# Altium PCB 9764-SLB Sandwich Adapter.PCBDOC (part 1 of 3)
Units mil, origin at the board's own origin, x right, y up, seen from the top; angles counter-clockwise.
Board outline 5593.84 x 1511.98 mil, 8 copper layers (Top Layer, MidLayer1, MidLayer2, MidLayer3, MidLayer4, MIdLayer5, MidLayer6, Bottom Layer); 137 components, 228 nets, 1508 pads, 0 vias.
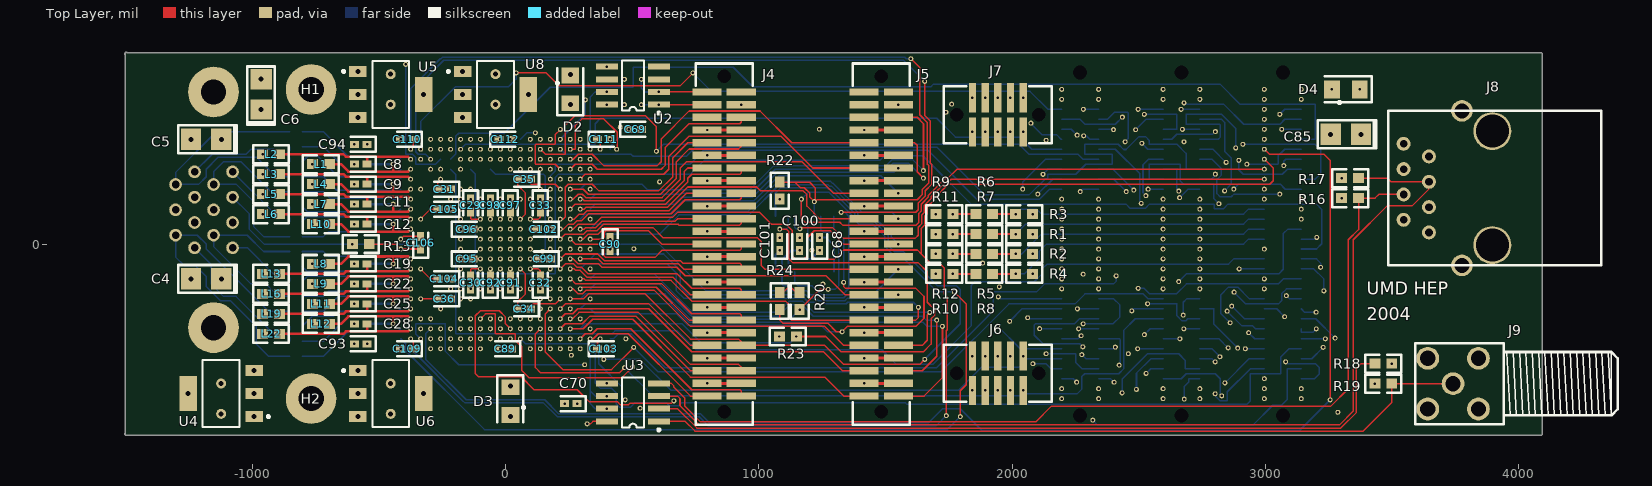
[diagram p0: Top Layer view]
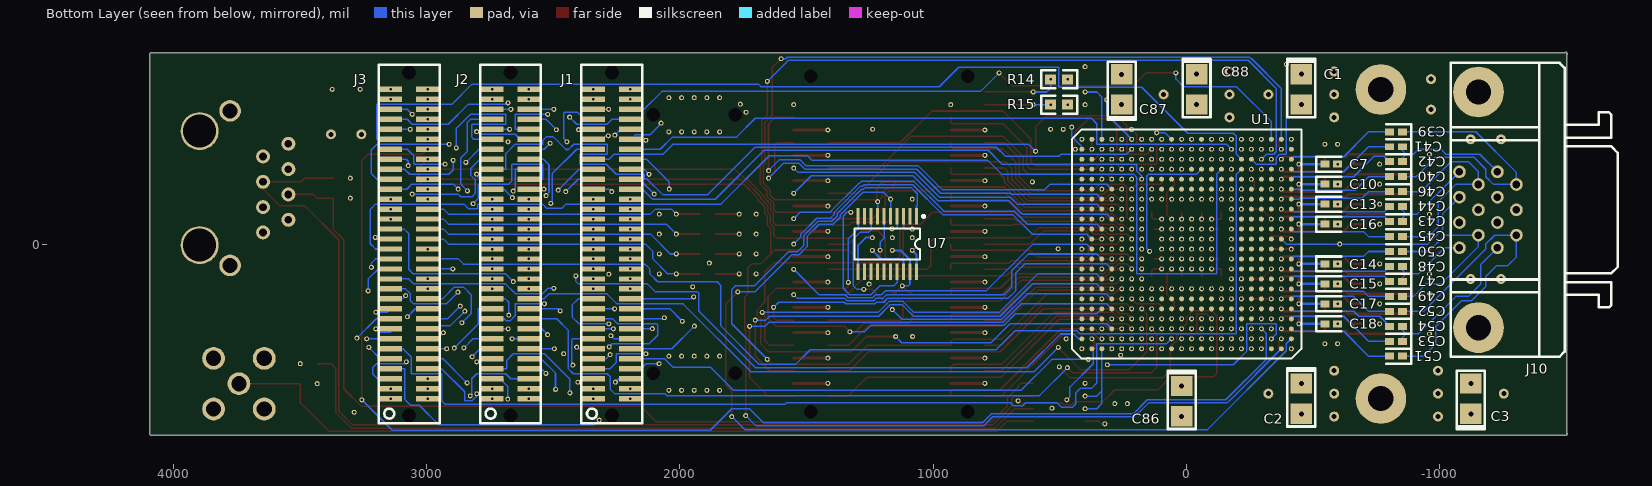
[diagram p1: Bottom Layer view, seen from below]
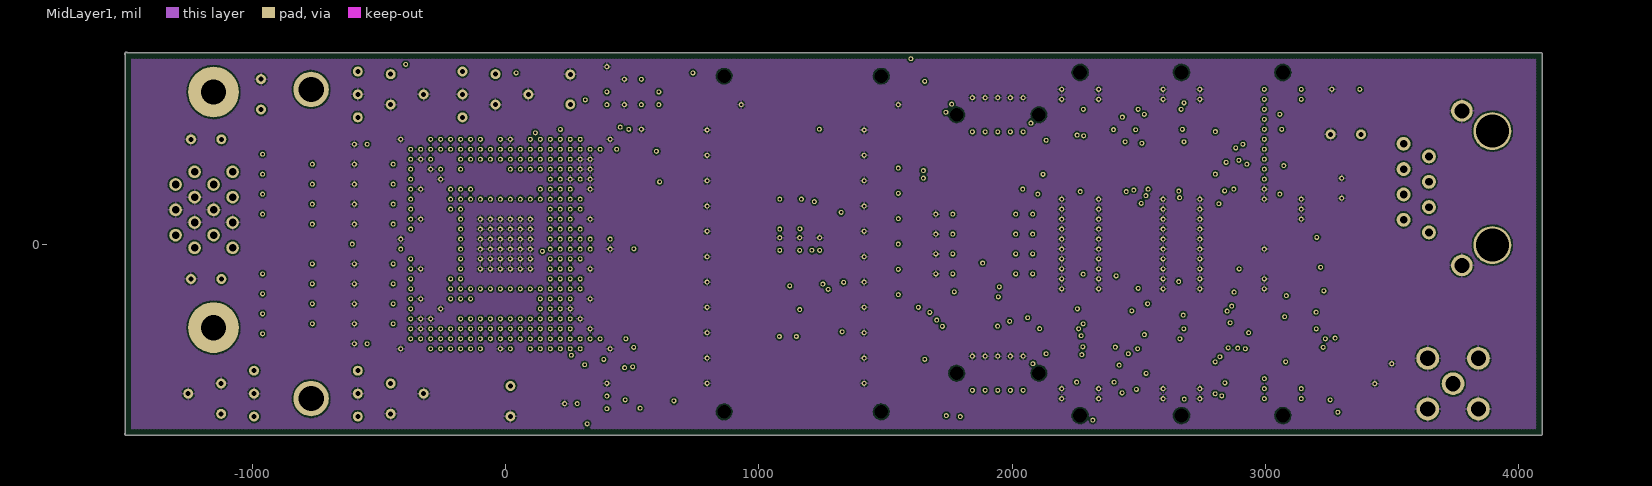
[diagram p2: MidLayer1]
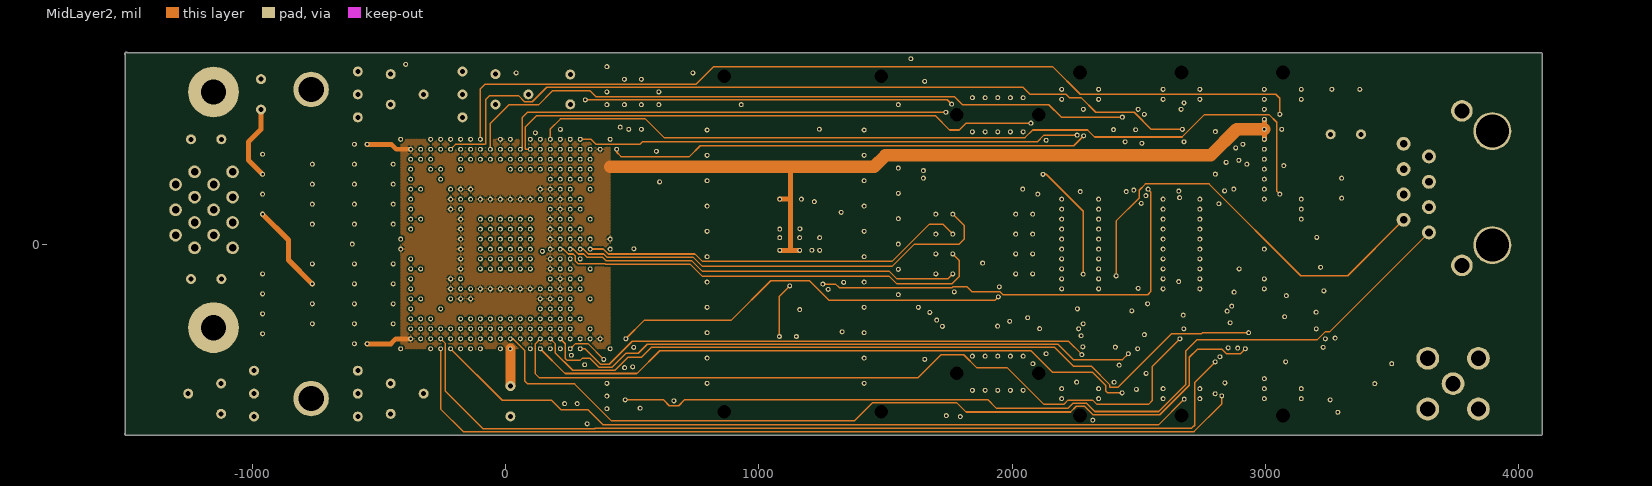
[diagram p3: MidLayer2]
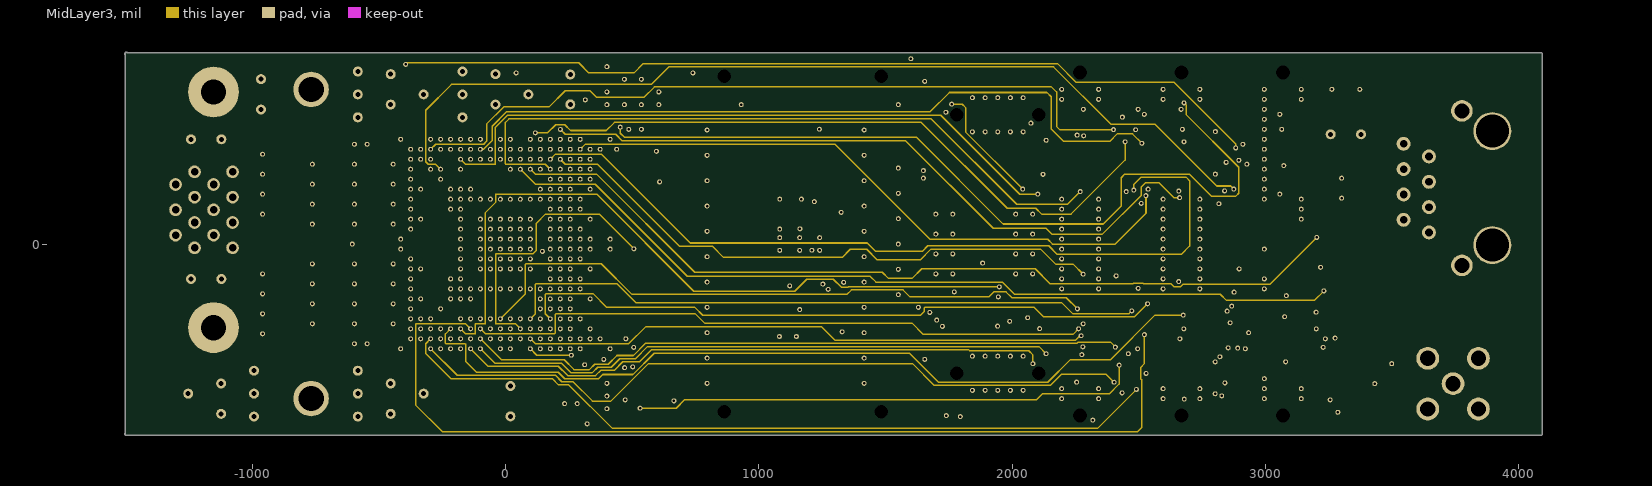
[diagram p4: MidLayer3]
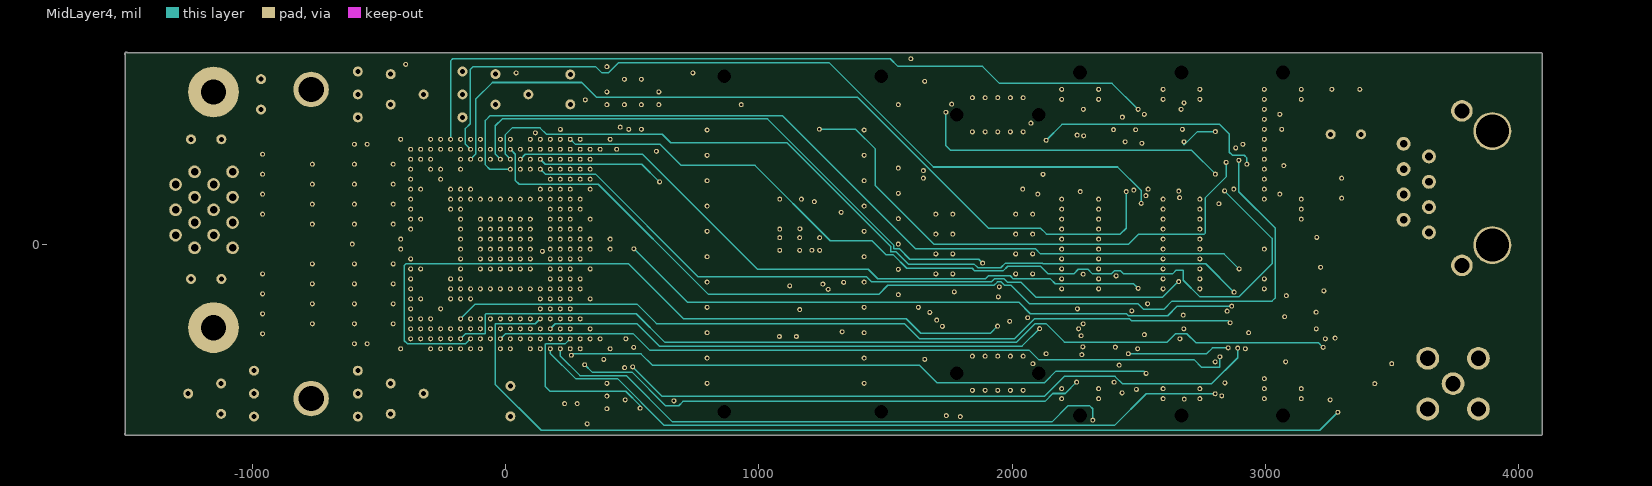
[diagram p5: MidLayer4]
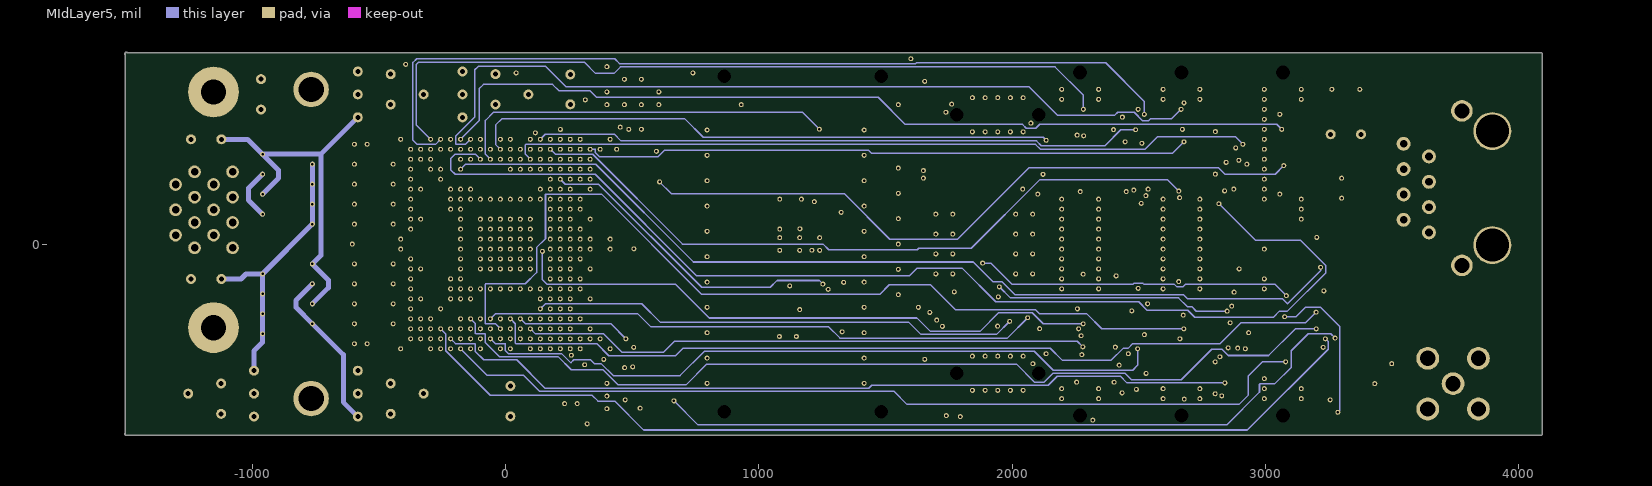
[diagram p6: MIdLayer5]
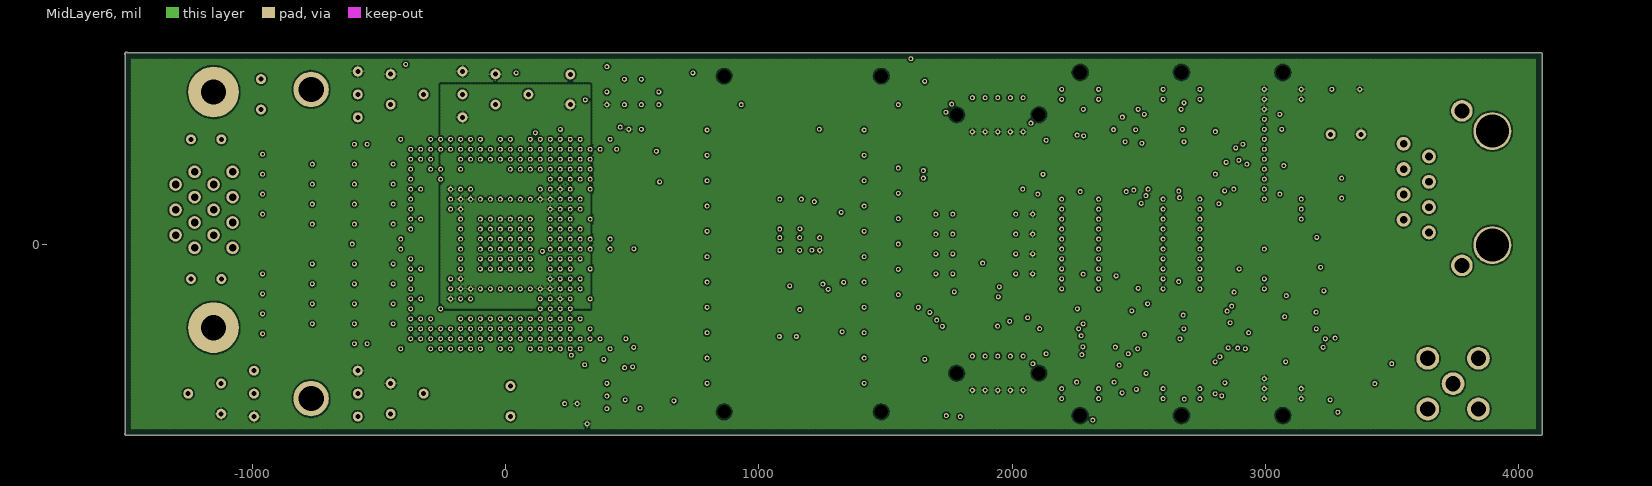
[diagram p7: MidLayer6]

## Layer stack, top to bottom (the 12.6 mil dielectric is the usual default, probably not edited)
Top Layer: signal copper 1.4
Dielectric: core 12.6, FR-4, Dk 4.8
MidLayer1: signal copper 1.4
Dielectric: prepreg 12.6, FR-4, Dk 4.8
MidLayer2: signal copper 1.4
Dielectric: core 12.6, FR-4, Dk 4.8
MidLayer3: signal copper 1.4
Dielectric: prepreg 12.6, FR-4, Dk 4.8
MidLayer4: signal copper 1.4
Dielectric: core 12.6, FR-4, Dk 4.8
MIdLayer5: signal copper 1.4
Dielectric: prepreg 12.6, FR-4, Dk 4.8
MidLayer6: signal copper 1.4
Dielectric: core 12.6, FR-4, Dk 4.8
Bottom Layer: signal copper 1.4

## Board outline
-1501.08,-747.3 -1501.08,747.3 cw(c-1496.85,750) -1501.01,752.8 cw(c-1496.06,751.97) -1492.08,755.01 4086.97,755.01 cw(c4086.97,750) 4091.98,750 4091.98,-750 cw(c4086.97,-750) 4086.97,-755.01 -1496.85,-755.01 cw(c-1496.85,-750)

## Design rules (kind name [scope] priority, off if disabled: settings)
Clearance [All] p1: gap=6
ComponentClearance [All] p1: gap=-10 collisioncheckmode=1
HoleSize [All] p1: absolutevalues=TRUE maxlimit=196.85 minlimit=9.84 maxpercent=80.000 minpercent=20.000
PlaneConnect PlaneConnect_1 [InNetClass('Power')] p1: planeconnectstyle=Relief reliefexpansion=20 reliefentries=4 reliefconductorwidth=10 reliefairgap=10
PlaneConnect [All] p2: planeconnectstyle=Relief reliefexpansion=15 reliefentries=4 reliefconductorwidth=6 reliefairgap=8
PolygonConnect [All] p1: connectstyle=Relief reliefconductorwidth=6 reliefentries=4 polygonreliefangle="90 Angle"
RoomDefinition "Power Supplies" [InComponentClass('Power Supplies')] p1: confinementstyle=ConfineIn formatcopy=TRUE outline -1751.97,-1348.43 25238.15,-1348.43 25238.15,5393.7 -1751.97,5393.7
RoomDefinition "Rocket IO" [InComponentClass('Rocket IO')] p2: confinementstyle=ConfineIn formatcopy=TRUE outline -1879.92,-1437.01 13938.15,-1437.01 13938.15,3464.57 -1879.92,3464.57
RoomDefinition "9764-SLB Sandwich Adapter" [InComponentClass('9764-SLB Sandwich Adapter')] p3: confinementstyle=ConfineIn formatcopy=TRUE outline -2361.85,-1750 18838.15,-1750 18838.15,9450 -2361.85,9450
RoutingLayers RoutingLayers_4 [InNet('GND')] p1: top layer_v5=FALSE mid layer 1_v5=TRUE mid layer 2_v5=FALSE mid layer 3_v5=FALSE mid layer 4_v5=FALSE mid layer 5_v5=FALSE mid layer 6_v5=FALSE bottom layer_v5=FALSE
RoutingLayers RoutingLayers_3 [InNet('+2.5V')] p2: top layer_v5=FALSE mid layer 1_v5=FALSE mid layer 2_v5=FALSE mid layer 3_v5=TRUE mid layer 4_v5=FALSE mid layer 5_v5=FALSE mid layer 6_v5=FALSE bottom layer_v5=FALSE
RoutingLayers RoutingLayers_2 [InNet('+3.3V')] p3: top layer_v5=FALSE mid layer 1_v5=FALSE mid layer 2_v5=TRUE mid layer 3_v5=FALSE mid layer 4_v5=FALSE mid layer 5_v5=FALSE mid layer 6_v5=FALSE bottom layer_v5=FALSE
RoutingLayers RoutingLayers_1 [InNet('+1.5V')] p4: top layer_v5=FALSE mid layer 1_v5=FALSE mid layer 2_v5=TRUE mid layer 3_v5=FALSE mid layer 4_v5=FALSE mid layer 5_v5=FALSE mid layer 6_v5=FALSE bottom layer_v5=FALSE
RoutingLayers [All] p5: top layer_v5=TRUE mid layer 1_v5=FALSE mid layer 2_v5=FALSE mid layer 3_v5=TRUE mid layer 4_v5=TRUE mid layer 5_v5=TRUE mid layer 6_v5=TRUE bottom layer_v5=TRUE
RoutingPriority RoutingPriority_1 [InNetClass('SLB/TTC')] p1: routingpriority=2
RoutingPriority [InNetClass('EPROM')] p2: routingpriority=0
RoutingVias [All] p1: holewidth=9.84 width=19.68 viastyle="Through Hole" minholewidth=9.84 minwidth=19.68 maxholewidth=78.74 maxwidth=157.48
SolderMaskExpansion [All] p1: expansion=4
TestPointUsage [All] p1: valid=0 allowmultiple=FALSE
Testpoint [All] p1: side=15 testpointundercomponent=TRUE minsize=40 maxsize=100 preferedsize=60 minholesize=0 maxholesize=40 preferedholesize=32 testpointgrid=1 style=1023 order=-539222988
Width [All] p1: maxlimit=100 minlimit=6 preferedwidth=10 toplayer_prefwidth=6 midlayer1_maxwidth=50 midlayer1_prefwidth=6 midlayer2_maxwidth=50 midlayer2_prefwidth=6 midlayer3_maxwidth=50 midlayer3_prefwidth=6 midlayer4_maxwidth=50 midlayer4_prefwidth=6 midlayer5_maxwidth=10 midlayer5_prefwidth=6 midlayer6_maxwidth=10 midlayer6_prefwidth=6 bottomlayer_prefwidth=6 minimp=50.000000 maximp=50.000000 favimp=50.000000
13 further rules are at their usual default settings.

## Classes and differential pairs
net class EPROM: CCLOCK DONE PROG_B PROM_INIT_B RECB3 TCK TDI TDI_F TDO TMS
net class 120MHz: ERRA ERRB ERRC ERRD IDLEA IDLEB IDLEC IDLED KCHA KCHB KCHC KCHD RECA0 RECA1 RECA2 RECA3 RECA4 RECA5 RECA6 RECA7 RECB0 RECB1 RECB2 RECB4 RECB5 RECB6 RECB7 RECC0 RECC1 RECC2 RECC3 RECC4 RECC5 RECC6 RECC7 RECD0 RECD1 RECD2 RECD3 RECD4 RECD5 RECD6 RECD7 RESETN TRSTN
net class RocketIO: \A \B \C \D \RX_A \RX_B \RX_C \RX_D \TX_A \TX_B \TX_C \TX_D A B C D NetR18_1 RX_A RX_B RX_C RX_D TX/R\X\ TX_A TX_B TX_C TX_D
net class SLB/TTC: LOC_C\S\ LOC_R/W\ LOCADD_0 LOCADD_1 LOCADD_2 LOCADD_3 LOCADD_4 LOCADD_5 LOCADD_6 LOCBUS_0 LOCBUS_1 LOCBUS_2 LOCBUS_3 LOCBUS_4 LOCBUS_5 LOCBUS_6 LOCBUS_7 LOCBUS_8 LOCBUS_9 LOCBUS_10 LOCBUS_11 LOCBUS_12 LOCBUS_13 LOCBUS_14 LOCBUS_15 SLB_ID TTC_BCR TTC_BRCST2 TTC_BRCST3 TTC_BRCST4 TTC_BRCST5 TTC_BRCST6 TTC_BRCST7 TTC_BRCST_STRB1 TTC_CLK_DES_1
net class Power: +1.5V +2.5V +3.3V AVCCAUX AVCCAUX1 AVCCAUX2 AVCCAUX3 AVCCAUX4 AVCCAUX5 AVCCAUX6 AVCCAUX7 AVCCAUX8 GND VTRX VTRX1 VTRX2 VTRX3 VTRX4 VTTX VTTX1 VTTX2 VTTX3 VTTX4
component class "Rocket IO": C39 C40 C41 C42 C43 C44 C45 C46 C47 C48 C49 C50 C51 C52 C53 C54 J10 J11
component class "9764-SLB Sandwich Adapter": J1 J2 J3 J4 J5 J6 J7 J8 J9 R1 R2 R3 R4 R5 R6 R7 R8 R9 R10 R11 R12 R13 R14 R15 R16 R17 R18 R19 U1 U2 U3
component class "Power Supplies": C1 C2 C3 C4 C5 C6 C7 C8 C9 C10 C11 C12 C13 C14 C15 C16 C17 C18 C19 C22 C25 C28 C29 C30 C31 C32 C33 C34 C35 C36 C61 C62 C63 C64 C65 C66 C67 C68 C69 C70 C71 C72 C73 C74 C75 C76 C77 C78 C79 C80 C81 C82 C83 C84 C85 C86 C87 C88 C89 C90 C91 C92 C93 C94 C95 C96 C97 C98 C99 C100 C101 C102 C103 C104 C105 C106 C107 C108 C109 C110 C111 C112 D2 D3 D4 H1 H2 H3 H4 H5 H6 L1 L2 L3 L4 L5 L6 L7 L8 L9 L10 L11 L12 L13 L16 L19 L22 R20 R22 R23 R24 U4 U5 U6 U7 U8
net class Clocks: BCO+ BCO- CLK+ CLK- NetJ8_4 NetJ8_5 NetJ9_1 PECL_OUT REFCLK REFCLK+ REFCLK- RX_BC0_INT+ RX_BC0_INT- RX_CLK_INT+ RX_CLK_INT- TP+ TP-

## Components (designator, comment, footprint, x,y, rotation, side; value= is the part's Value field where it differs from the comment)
C1 "10 uF" CT3528-1411 -452.76,610.24 r270 bottom
C2 "10 uF" CT3528-1411 -452.76,-610.24 r270 bottom
C3 "10 uF" CT3528-1411 -1122.05,-610.24 r90 bottom
C4 "10 uF" CT3528-1411 -1181.1,-137.8 r180 top
C5 "10 uF" CT3528-1411 -1181.1,413.39 r180 top
C6 "330 uF" CT3528-1411 -964.57,590.55 r90 top
C7 "1 uF" CC1005-0402 -570.87,314.96 r180 bottom
C8 "1 uF" CC1005-0402 -570.87,314.96 r180 top
C9 "1 uF" CC1005-0402 -570.87,236.22 r180 top
C10 "1 uF" CC1005-0402 -570.87,236.22 r180 bottom
C11 "1 uF" CC1005-0402 -570.87,157.48 r180 top
C12 "1 uF" CC1005-0402 -570.87,78.74 r180 top
C13 "1 uF" CC1005-0402 -570.87,157.48 r180 bottom
C14 "1 uF" CC1005-0402 -570.87,-78.74 r180 bottom
C15 "1 uF" CC1005-0402 -570.87,-157.48 r180 bottom
C16 "1 uF" CC1005-0402 -570.87,78.74 r180 bottom
C17 "1 uF" CC1005-0402 -570.87,-236.22 r180 bottom
C18 "1 uF" CC1005-0402 -570.87,-314.96 r180 bottom
C19 "1 uF" CC1005-0402 -570.87,-78.74 r180 top
C22 "1 uF" CC1005-0402 -570.87,-157.48 r180 top
C25 "1 uF" CC1005-0402 -570.87,-236.22 r180 top
C28 "1 uF" CC1005-0402 -570.87,-314.96 r180 top
C29 ".1 uF" CC1005-0402 -137.8,152.17 r270 top
C30 ".1 uF" CC1005-0402 -137.8,-152.17 r90 top
C31 ".1 uF" CC1005-0402 -241.54,216.54 r180 top
C32 ".1 uF" CC1005-0402 137.8,-152.17 r90 top
C33 ".1 uF" CC1005-0402 137.8,152.17 r270 top
C34 ".1 uF" CC1005-0402 73.43,-255.91 r180 top
C35 ".1 uF" CC1005-0402 73.43,255.91 r180 top
C36 ".1 uF" CC1005-0402 -241.54,-216.54 r180 top
C39 "1 uF" CC1005-0402 -826.77,442.91 r0 bottom
C40 "1 uF" CC1005-0402 -826.77,265.75 r0 bottom
C41 "1 uF" CC1005-0402 -826.77,383.86 r0 bottom
C42 "1 uF" CC1005-0402 -826.77,324.8 r0 bottom
C43 "1 uF" CC1005-0402 -826.77,88.58 r0 bottom
C44 "1 uF" CC1005-0402 -826.77,147.64 r0 bottom
C45 "1 uF" CC1005-0402 -826.77,29.53 r0 bottom
C46 "1 uF" CC1005-0402 -826.77,206.69 r0 bottom
C47 "1 uF" CC1005-0402 -826.77,-147.64 r0 bottom
C48 "1 uF" CC1005-0402 -826.77,-88.58 r0 bottom
C49 "1 uF" CC1005-0402 -826.77,-206.69 r0 bottom
C50 "1 uF" CC1005-0402 -826.77,-29.53 r0 bottom
C51 "1 uF" CC1005-0402 -826.77,-442.91 r0 bottom
C52 "1 uF" CC1005-0402 -826.77,-265.75 r0 bottom
C53 "1 uF" CC1005-0402 -826.77,-383.86 r0 bottom
C54 "1 uF" CC1005-0402 -826.77,-324.8 r0 bottom
C68 ".1 uF" CC1005-0402 1240.16,0 r90 top
C69 ".1 uF" CC1005-0402 511.81,452.76 r0 top
C70 ".1 uF" CC1005-0402 258.27,-629.92 r180 top
C85 "330 uF" CT3528-1411 3316.93,433.07 r180 top
C86 "330 uF" CT3528-1411 19.69,-620.08 r270 bottom
C87 "330 uF" CT3528-1411 255.91,610.24 r90 bottom
C88 "330 uF" CT3528-1411 -39.37,610.24 r270 bottom
C89 ".1 uF" CC1005-0402 0,-413.39 r180 top
C90 ".1 uF" CC1005-0402 413.39,0 r270 top
C91 ".1 uF" CC1005-0402 19.69,-152.17 r90 top
C92 ".1 uF" CC1005-0402 -59.06,-152.17 r90 top
C93 ".1 uF" CC1005-0402 -570.87,-393.7 r180 top
C94 ".1 uF" CC1005-0402 -570.87,393.7 r180 top
C95 ".1 uF" CC1005-0402 -152.17,-59.06 r0 top
C96 ".1 uF" CC1005-0402 -152.17,59.06 r0 top
C97 ".1 uF" CC1005-0402 19.69,152.17 r270 top
C98 ".1 uF" CC1005-0402 -59.06,152.17 r270 top
C99 ".1 uF" CC1005-0402 152.17,-59.06 r180 top
C100 ".1 uF" CC1005-0402 1161.42,0 r90 top
C101 ".1 uF" CC1005-0402 1082.68,0 r90 top
C102 ".1 uF" CC1005-0402 152.17,59.06 r180 top
C103 ".1 uF" CC1005-0402 388.39,-413.39 r0 top
C104 ".1 uF" CC1005-0402 -241.54,-137.8 r180 top
C105 ".1 uF" CC1005-0402 -241.54,137.8 r180 top
C106 ".1 uF" CC1005-0402 -334.65,5.32 r90 top
C109 ".1 uF" CC1005-0402 -388.39,-413.39 r180 top
C110 ".1 uF" CC1005-0402 -388.39,413.39 r180 top
C111 ".1 uF" CC1005-0402 388.39,413.39 r0 top
C112 ".1 uF" CC1005-0402 0,413.39 r0 top
D2 "LED" "HSMx-C150 LED" 255.91,610.24 r90 top
D3 "LED" "HSMx-C150 LED" 19.69,-620.08 r270 top
D4 "LED" "HSMx-C150 LED" 3316.93,610.24 r180 top
H1 "MH" "MOUNTING HOLE"#1 -767.72,669.29 r0 top
H2 "MH" "MOUNTING HOLE"#2 -787.4,-649.61 r0 top
J1 "MHDR2X32" MOLEX-71436-0464 2268.15,0 r0 bottom locked
J2 "MHDR2X32" MOLEX-71436-0464 2668.15,0 r0 bottom locked
J3 "MHDR2X32" MOLEX-71436-0464 3068.15,0 r0 bottom locked
J4 "" SAMTEC-TFM-150-XX-X-D 863.15,0 r180 top locked
J5 "" SAMTEC-TFM-150-XX-X-D 1483.15,0 r180 top locked
J6 "Connector 2X5" SAMTEC-TFM-110-XX-X-D 1943.15,-510 r90 top
J7 "Connector 2X5" SAMTEC-TFM-110-XX-X-D 1943.15,510 r90 top
J8 "558342-1" 558342-1 3894.97,220.56 r180 top
J9 "COAX" JOHNSON-SMA 3740.16,-551.18 r0 top
J10 "MDR-14" MDR-14 -1151.85,135 r90 bottom locked
L1 "1000" CR1608-0603 -728.35,314.96 r180 top
L2 "600" CR1608-0603 -925.2,354.33 r180 top
L3 "600" CR1608-0603 -925.2,275.59 r180 top
L4 "1000" CR1608-0603 -728.35,236.22 r180 top
L5 "600" CR1608-0603 -925.2,196.85 r180 top
L6 "600" CR1608-0603 -925.2,118.11 r180 top
L7 "600" CR1608-0603 -728.35,157.48 r180 top
L8 "600" CR1608-0603 -728.35,-78.74 r180 top
L9 "600" CR1608-0603 -728.35,-157.48 r180 top
L10 "600" CR1608-0603 -728.35,78.74 r180 top
L11 "600" CR1608-0603 -728.35,-236.22 r180 top
L12 "600" CR1608-0603 -728.35,-314.96 r180 top
L13 "600" CR1608-0603 -925.2,-118.11 r180 top
L16 "600" CR1608-0603 -925.2,-196.85 r180 top
L19 "600" CR1608-0603 -925.2,-275.59 r180 top
L22 "600" CR1608-0603 -925.2,-354.33 r180 top
R1 "130" CR1608-0603 2047.24,39.37 r180 top
R2 "130" CR1608-0603 2047.24,-39.37 r180 top
R3 "130" CR1608-0603 2047.24,118.11 r180 top
R4 "130" CR1608-0603 2047.24,-118.11 r180 top
R5 "27" CR1608-0603 1889.76,-39.37 r180 top
R6 "27" CR1608-0603 1889.76,118.11 r180 top
R7 "27" CR1608-0603 1889.76,39.37 r180 top
R8 "27" CR1608-0603 1889.76,-118.11 r180 top
R9 "56" CR1608-0603 1732.28,118.11 r0 top
R10 "56" CR1608-0603 1732.28,-118.11 r0 top
R11 "56" CR1608-0603 1732.28,39.37 r0 top
R12 "56" CR1608-0603 1732.28,-39.37 r0 top
R13 "50" CR1608-0603 -570.87,0 r180 top
R14 "50" CR1608-0603 503.15,650 r180 bottom
R15 "50" CR1608-0603 503.15,550 r180 bottom
R16 "50" CR1608-0603 3333.55,181.19 r180 top
R17 "50" CR1608-0603 3333.55,259.93 r180 top
R18 "50" CR1608-0603 3464.57,-472.44 r0 top
R19 "50" CR1608-0603 3464.57,-551.18 r180 top
R20 "4.7 k" CR1608-0603 1161.42,-225 r90 top
R22 "4.7 k" CR1608-0603 1082.68,210.63 r270 top
R23 "4.7 k" CR1608-0603 1115,-365 r180 top
R24 "4.7 k" CR1608-0603 1082.68,-225 r90 top
U1 "XC2VP7-5FG456C" FG456 0,0 r270 bottom locked
U2 "MC100EPT22D" 751-06 503.15,625 r90 top
U3 "MC100EPT22D" 751-06 503.15,-625 r90 top
U4 "#NAME?" SOT-223 -1122.05,-590.55 r90 top
U5 "#NAME?" SOT-223 -452.76,590.55 r270 top
U6 "#NAME?" SOT-223 -452.76,-590.55 r270 top
U7 "XCF04SVO20C" VO20 1181.1,0 r0 bottom
U8 "#NAME?" SOT-223 -39.37,590.55 r270 top

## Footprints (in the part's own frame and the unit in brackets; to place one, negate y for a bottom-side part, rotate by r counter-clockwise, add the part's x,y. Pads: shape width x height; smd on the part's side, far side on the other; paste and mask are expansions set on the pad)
751-06 [mm] "Small Outline; 8 Leads; Body Width 3.9 mm; Pitch 1.27 mm"
  rect 0.6x2.2 smd: 1(-1.905,-2.6) 2(-0.635,-2.6) 3(0.635,-2.6) 4(1.905,-2.6) 5(1.905,2.6) 6(0.635,2.6) 7(-0.635,2.6) 8(-1.905,2.6)
  silkscreen extent -2.88,-2.72 2.5,1.1
558342-1 [mil] "8 pin Sheilded Right Angle RJ-45 Cat 5 Connector"
  round 150 hole 130 unplated: 0(0,225) 0(0,-225)
  round 85 hole 60: 0(120,305) 0(120,-305)
  round 55 hole 30: 1(350,125) 2(250,175) 3(250,75) 4(250,-25) 5(350,25) 6(350,-75) 7(350,-175) 8(250,-125)
  silkscreen extent -430,-305 410,305
CC1005-0402 [mm]
  rect 0.9x0.7 smd: 1(-0.635,0) 2(0.635,0)
  silkscreen extent -1.5,-0.75 1,0.75
CR1608-0603 [mm]
  rect 1.1x1 smd: 1(-0.85,0) 2(0.85,0)
  silkscreen extent -1.8,-0.9 1.8,0.9
CT3528-1411 [mil] "Tantalum Electrolytic Capacitor"
  rect 80x85 smd: 1(-60,0) 2(60,0)
  silkscreen extent -120,-55 110,55
FG456 [mm]
  round 0.5 hole 0.25: A1(-10.5,10.5) A11(-0.5,10.5) A12(0.5,10.5) A22(10.5,10.5) AA2(-9.5,-9.5) AA21(9.5,-9.5) AB1(-10.5,-10.5) AB11(-0.5,-10.5) AB12(0.5,-10.5) AB22(10.5,-10.5) B2(-9.5,9.5) B3(-8.5,9.5) B4(-7.5,9.5) B5(-6.5,9.5) B6(-5.5,9.5) B7(-4.5,9.5) B8(-3.5,9.5) B9(-2.5,9.5) B10(-1.5,9.5) B13(1.5,9.5) B14(2.5,9.5) B15(3.5,9.5) B16(4.5,9.5) B17(5.5,9.5) B18(6.5,9.5) B19(7.5,9.5) B20(8.5,9.5) B21(9.5,9.5) C2(-9.5,8.5) C3(-8.5,8.5) C6(-5.5,8.5) C9(-2.5,8.5) C14(2.5,8.5) C17(5.5,8.5) C19(7.5,8.5) C20(8.5,8.5) C21(9.5,8.5) D1(-10.5,7.5) D2(-9.5,7.5) D3(-8.5,7.5) D4(-7.5,7.5) D19(7.5,7.5) D20(8.5,7.5) D21(9.5,7.5) D22(10.5,7.5) E1(-10.5,6.5) E2(-9.5,6.5) E4(-7.5,6.5) E5(-6.5,6.5) E18(6.5,6.5) E20(8.5,6.5) E21(9.5,6.5) E22(10.5,6.5) F1(-10.5,5.5) F2(-9.5,5.5) F6(-5.5,5.5) F7(-4.5,5.5) F8(-3.5,5.5) F15(3.5,5.5) F16(4.5,5.5) F17(5.5,5.5) F20(8.5,5.5) F21(9.5,5.5) F22(10.5,5.5) G1(-10.5,4.5) G2(-9.5,4.5) G3(-8.5,4.5) G4(-7.5,4.5) G6(-5.5,4.5) G7(-4.5,4.5) G8(-3.5,4.5) G9(-2.5,4.5) G10(-1.5,4.5) G11(-0.5,4.5) G12(0.5,4.5) G13(1.5,4.5) G14(2.5,4.5) G15(3.5,4.5) G16(4.5,4.5) G17(5.5,4.5) G19(7.5,4.5) G20(8.5,4.5) G21(9.5,4.5) G22(10.5,4.5) H1(-10.5,3.5) H2(-9.5,3.5) H3(-8.5,3.5) H6(-5.5,3.5) H7(-4.5,3.5) H16(4.5,3.5) H17(5.5,3.5) H19(7.5,3.5) H20(8.5,3.5) H21(9.5,3.5) H22(10.5,3.5) J1(-10.5,2.5) J2(-9.5,2.5) J3(-8.5,2.5) J7(-4.5,2.5) J9(-2.5,2.5) J10(-1.5,2.5) J11(-0.5,2.5) J12(0.5,2.5) J13(1.5,2.5) J14(2.5,2.5) J16(4.5,2.5) J19(7.5,2.5) J20(8.5,2.5) J21(9.5,2.5) J22(10.5,2.5) K2(-9.5,1.5) K3(-8.5,1.5) K7(-4.5,1.5) K9(-2.5,1.5) K10(-1.5,1.5) K11(-0.5,1.5) K12(0.5,1.5) K13(1.5,1.5) K14(2.5,1.5) K16(4.5,1.5) K19(7.5,1.5) K20(8.5,1.5) K21(9.5,1.5) L1(-10.5,0.5) L2(-9.5,0.5) L3(-8.5,0.5) L7(-4.5,0.5) L9(-2.5,0.5) L10(-1.5,0.5) L11(-0.5,0.5) L12(0.5,0.5) L13(1.5,0.5) L14(2.5,0.5) L16(4.5,0.5) L19(7.5,0.5) L20(8.5,0.5) L21(9.5,0.5) L22(10.5,0.5) M1(-10.5,-0.5) M2(-9.5,-0.5) M3(-8.5,-0.5) M4(-7.5,-0.5) M7(-4.5,-0.5) M9(-2.5,-0.5) M10(-1.5,-0.5) M11(-0.5,-0.5) M12(0.5,-0.5) M13(1.5,-0.5) M14(2.5,-0.5) M16(4.5,-0.5) M19(7.5,-0.5) M20(8.5,-0.5) M21(9.5,-0.5) M22(10.5,-0.5) N2(-9.5,-1.5) N3(-8.5,-1.5) N4(-7.5,-1.5) N7(-4.5,-1.5) N9(-2.5,-1.5) N10(-1.5,-1.5) N11(-0.5,-1.5) N12(0.5,-1.5) N13(1.5,-1.5) N14(2.5,-1.5) N16(4.5,-1.5) N19(7.5,-1.5) N20(8.5,-1.5) N21(9.5,-1.5) P1(-10.5,-2.5) P2(-9.5,-2.5) P3(-8.5,-2.5) P4(-7.5,-2.5) P7(-4.5,-2.5) P9(-2.5,-2.5) P10(-1.5,-2.5) P11(-0.5,-2.5) P12(0.5,-2.5) P13(1.5,-2.5) P14(2.5,-2.5) P16(4.5,-2.5) P19(7.5,-2.5) P20(8.5,-2.5) P21(9.5,-2.5) P22(10.5,-2.5) R1(-10.5,-3.5) R2(-9.5,-3.5) R3(-8.5,-3.5) R4(-7.5,-3.5) R6(-5.5,-3.5) R7(-4.5,-3.5) R16(4.5,-3.5) R17(5.5,-3.5) R18(6.5,-3.5) R19(7.5,-3.5) R20(8.5,-3.5) R21(9.5,-3.5) R22(10.5,-3.5) T1(-10.5,-4.5) T2(-9.5,-4.5) T3(-8.5,-4.5) T4(-7.5,-4.5) T5(-6.5,-4.5) T6(-5.5,-4.5) T7(-4.5,-4.5) T8(-3.5,-4.5) T9(-2.5,-4.5) T10(-1.5,-4.5) T11(-0.5,-4.5) T12(0.5,-4.5) T13(1.5,-4.5) T14(2.5,-4.5) T15(3.5,-4.5) T16(4.5,-4.5) T17(5.5,-4.5) T18(6.5,-4.5) T19(7.5,-4.5) T20(8.5,-4.5) T21(9.5,-4.5) T22(10.5,-4.5) U1(-10.5,-5.5) U2(-9.5,-5.5) U3(-8.5,-5.5) U4(-7.5,-5.5) U5(-6.5,-5.5) U6(-5.5,-5.5) U7(-4.5,-5.5) U8(-3.5,-5.5) U9(-2.5,-5.5) U10(-1.5,-5.5) U11(-0.5,-5.5) U12(0.5,-5.5) U13(1.5,-5.5) U14(2.5,-5.5) U15(3.5,-5.5) U16(4.5,-5.5) U17(5.5,-5.5) U18(6.5,-5.5) U19(7.5,-5.5) U20(8.5,-5.5) U21(9.5,-5.5) U22(10.5,-5.5) V1(-10.5,-6.5) V2(-9.5,-6.5) V3(-8.5,-6.5) V4(-7.5,-6.5) V5(-6.5,-6.5) V6(-5.5,-6.5) V7(-4.5,-6.5) V8(-3.5,-6.5) V9(-2.5,-6.5) V10(-1.5,-6.5) V11(-0.5,-6.5) V12(0.5,-6.5) V13(1.5,-6.5) V14(2.5,-6.5) V15(3.5,-6.5) V16(4.5,-6.5) V17(5.5,-6.5) V18(6.5,-6.5) V19(7.5,-6.5) V20(8.5,-6.5) V21(9.5,-6.5) V22(10.5,-6.5) W1(-10.5,-7.5) W2(-9.5,-7.5) W3(-8.5,-7.5) W4(-7.5,-7.5) W5(-6.5,-7.5) W7(-4.5,-7.5) W8(-3.5,-7.5) W10(-1.5,-7.5) W11(-0.5,-7.5) W12(0.5,-7.5) W13(1.5,-7.5) W15(3.5,-7.5) W16(4.5,-7.5) W19(7.5,-7.5) W21(9.5,-7.5) W22(10.5,-7.5) Y2(-9.5,-8.5) Y3(-8.5,-8.5) Y4(-7.5,-8.5) Y5(-6.5,-8.5) Y6(-5.5,-8.5) Y9(-2.5,-8.5) Y11(-0.5,-8.5) Y12(0.5,-8.5) Y14(2.5,-8.5) Y17(5.5,-8.5) Y20(8.5,-8.5) Y21(9.5,-8.5)
  round 0.5 smd: A2(-9.5,10.5) A3(-8.5,10.5) A4(-7.5,10.5) A5(-6.5,10.5) A6(-5.5,10.5) A7(-4.5,10.5) A8(-3.5,10.5) A9(-2.5,10.5) A10(-1.5,10.5) A13(1.5,10.5) A14(2.5,10.5) A15(3.5,10.5) A16(4.5,10.5) A17(5.5,10.5) A18(6.5,10.5) A19(7.5,10.5) A20(8.5,10.5) A21(9.5,10.5) AA1(-10.5,-9.5) AA3(-8.5,-9.5) AA4(-7.5,-9.5) AA5(-6.5,-9.5) AA6(-5.5,-9.5) AA7(-4.5,-9.5) AA8(-3.5,-9.5) AA9(-2.5,-9.5) AA10(-1.5,-9.5) AA11(-0.5,-9.5) AA12(0.5,-9.5) AA13(1.5,-9.5) AA14(2.5,-9.5) AA15(3.5,-9.5) AA16(4.5,-9.5) AA17(5.5,-9.5) AA18(6.5,-9.5) AA19(7.5,-9.5) AA20(8.5,-9.5) AA22(10.5,-9.5) AB2(-9.5,-10.5) AB3(-8.5,-10.5) AB4(-7.5,-10.5) AB5(-6.5,-10.5) AB6(-5.5,-10.5) AB7(-4.5,-10.5) AB8(-3.5,-10.5) AB9(-2.5,-10.5) AB10(-1.5,-10.5) AB13(1.5,-10.5) AB14(2.5,-10.5) AB15(3.5,-10.5) AB16(4.5,-10.5) AB17(5.5,-10.5) AB18(6.5,-10.5) AB19(7.5,-10.5) AB20(8.5,-10.5) AB21(9.5,-10.5) B1(-10.5,9.5) B11(-0.5,9.5) B12(0.5,9.5) B22(10.5,9.5) C1(-10.5,8.5) C4(-7.5,8.5) C5(-6.5,8.5) C7(-4.5,8.5) C8(-3.5,8.5) C10(-1.5,8.5) C11(-0.5,8.5) C12(0.5,8.5) C13(1.5,8.5) C15(3.5,8.5) C16(4.5,8.5) C18(6.5,8.5) C22(10.5,8.5) D5(-6.5,7.5) D6(-5.5,7.5) D7(-4.5,7.5) D8(-3.5,7.5) D9(-2.5,7.5) D10(-1.5,7.5) D11(-0.5,7.5) D12(0.5,7.5) D13(1.5,7.5) D14(2.5,7.5) D15(3.5,7.5) D16(4.5,7.5) D17(5.5,7.5) D18(6.5,7.5) E3(-8.5,6.5) E6(-5.5,6.5) E7(-4.5,6.5) E8(-3.5,6.5) E9(-2.5,6.5) E10(-1.5,6.5) E11(-0.5,6.5) E12(0.5,6.5) E13(1.5,6.5) E14(2.5,6.5) E15(3.5,6.5) E16(4.5,6.5) E17(5.5,6.5) E19(7.5,6.5) F3(-8.5,5.5) F4(-7.5,5.5) F5(-6.5,5.5) F9(-2.5,5.5) F10(-1.5,5.5) F11(-0.5,5.5) F12(0.5,5.5) F13(1.5,5.5) F14(2.5,5.5) F18(6.5,5.5) F19(7.5,5.5) G5(-6.5,4.5) G18(6.5,4.5) H4(-7.5,3.5) H5(-6.5,3.5) H18(6.5,3.5) J4(-7.5,2.5) J5(-6.5,2.5) J6(-5.5,2.5) J17(5.5,2.5) J18(6.5,2.5) K1(-10.5,1.5) K4(-7.5,1.5) K5(-6.5,1.5) K6(-5.5,1.5) K17(5.5,1.5) K18(6.5,1.5) K22(10.5,1.5) L4(-7.5,0.5) L5(-6.5,0.5) L6(-5.5,0.5) L17(5.5,0.5) L18(6.5,0.5) M5(-6.5,-0.5) M6(-5.5,-0.5) M17(5.5,-0.5) M18(6.5,-0.5) N1(-10.5,-1.5) N5(-6.5,-1.5) N6(-5.5,-1.5) N17(5.5,-1.5) N18(6.5,-1.5) N22(10.5,-1.5) P5(-6.5,-2.5) P6(-5.5,-2.5) P17(5.5,-2.5) P18(6.5,-2.5) R5(-6.5,-3.5) W6(-5.5,-7.5) W9(-2.5,-7.5) W14(2.5,-7.5) W17(5.5,-7.5) W18(6.5,-7.5) W20(8.5,-7.5) Y1(-10.5,-8.5) Y7(-4.5,-8.5) Y8(-3.5,-8.5) Y10(-1.5,-8.5) Y13(1.5,-8.5) Y15(3.5,-8.5) Y16(4.5,-8.5) Y18(6.5,-8.5) Y19(7.5,-8.5) Y22(10.5,-8.5)
  silkscreen extent -11.5,-11.5 11.5,11.5
"HSMx-C150 LED" [mil] "Surface Mount Chip LED"
  rect 62x70 smd: 1(-55,0) 2(55,0)
  silkscreen extent -102,-51 83,56
JOHNSON-SMA [mil] "Johnson-SMA"
  round 90 hole 60: 1(0,0) 2(-100,-100) 2(-100,100) 2(100,-100) 2(100,100)
  silkscreen extent -150,-160 650,160
MDR-14 [mil]
  round 200 hole 100: 0(-465,0) 0(465,0)
  round 50 hole 30: 1(150,75) 2(100,0) 3(50,75) 4(0,0) 5(-50,75) 6(-100,0) 7(-150,75) 8(150,-75) 9(100,-150) 10(50,-75) 11(0,-150) 12(-50,-75) 13(-100,-150) 14(-150,-75)
  silkscreen extent -580,-550 580,110
MOLEX-71436-0464 [mm] "64 Position Male Mezzanine Connector"
  round 0 hole 1.4 unplated: 0(0,-17.2) 0(0,17.2)
  rect 2.3x0.533 smd: 1(1.85,15.5) 2(-1.85,15.5) 3(1.85,14.5) 4(-1.85,14.5) 5(1.85,13.5) 6(-1.85,13.5) 7(1.85,12.5) 8(-1.85,12.5) 9(1.85,11.5) 10(-1.85,11.5) 11(1.85,10.5) 12(-1.85,10.5) 13(1.85,9.5) 14(-1.85,9.5) 15(1.85,8.5) 16(-1.85,8.5) 17(1.85,7.5) 18(-1.85,7.5) 19(1.85,6.5) 20(-1.85,6.5) 21(1.85,5.5) 22(-1.85,5.5) 23(1.85,4.5) 24(-1.85,4.5) 25(1.85,3.5) 26(-1.85,3.5) 27(1.85,2.5) 28(-1.85,2.5) 29(1.85,1.5) 30(-1.85,1.5) 31(1.85,0.5) 32(-1.85,0.5) 33(1.85,-0.5) 34(-1.85,-0.5) 35(1.85,-1.5) 36(-1.85,-1.5) 37(1.85,-2.5) 38(-1.85,-2.5) 39(1.85,-3.5) 40(-1.85,-3.5) 41(1.85,-4.5) 42(-1.85,-4.5) 43(1.85,-5.5) 44(-1.85,-5.5) 45(1.85,-6.5) 46(-1.85,-6.5) 47(1.85,-7.5) 48(-1.85,-7.5) 49(1.85,-8.5) 50(-1.85,-8.5) 51(1.85,-9.5) 52(-1.85,-9.5) 53(1.85,-10.5) 54(-1.85,-10.5) 55(1.85,-11.5) 56(-1.85,-11.5) 57(1.85,-12.5) 58(-1.85,-12.5) 59(1.85,-13.5) 60(-1.85,-13.5) 61(1.85,-14.5) 62(-1.85,-14.5) 63(1.85,-15.5) 64(-1.85,-15.5)
  silkscreen extent -3.05,-17.95 3.05,17.95
"MOUNTING HOLE"#1 [mil]
  round 200 / inner round 140 / far side round 200 hole 100: 1(0.87,-59.29)
"MOUNTING HOLE"#2 [mil]
  round 200 / inner round 140 / far side round 200 hole 100: 1(20.55,39.61)
SAMTEC-TFM-110-XX-X-D [mil]
  round 0 hole 53 unplated: 0(0,162.5) 0(0,-162.5)
  rect 115x29 smd: 1(-67.5,100) 2(-67.5,50) 3(-67.5,0) 4(-67.5,-50) 5(-67.5,-100) 6(67.5,100) 7(67.5,50) 8(67.5,0) 9(67.5,-50) 10(67.5,-100)
  silkscreen extent -113,-212 113,212
SAMTEC-TFM-150-XX-X-D [mil] "50 Pin Surface Mount Connector"
  round 0 hole 53 unplated: 0(0,662.5) 0(0,-662.5)
  rect 115x29 smd: 1(-67.5,600) 2(-67.5,550) 3(-67.5,500) 4(-67.5,450) 5(-67.5,400) 6(-67.5,350) 7(-67.5,300) 8(-67.5,250) 9(-67.5,200) 10(-67.5,150) 11(-67.5,100) 12(-67.5,50) 13(-67.5,0) 14(-67.5,-50) 15(-67.5,-100) 16(-67.5,-150) 17(-67.5,-200) 18(-67.5,-250) 19(-67.5,-300) 20(-67.5,-350) 21(-67.5,-400) 22(-67.5,-450) 23(-67.5,-500) 24(-67.5,-550) 25(-67.5,-600) 26(67.5,600) 27(67.5,550) 28(67.5,500) 29(67.5,450) 30(67.5,400) 31(67.5,350) 32(67.5,300) 33(67.5,250) 34(67.5,200) 35(67.5,150) 36(67.5,100) 37(67.5,50) 38(67.5,0) 39(67.5,-50) 40(67.5,-100) 41(67.5,-150) 42(67.5,-200) 43(67.5,-250) 44(67.5,-300) 45(67.5,-350) 46(67.5,-400) 47(67.5,-450) 48(67.5,-500) 49(67.5,-550) 50(67.5,-600)
  silkscreen extent -113,-712 113,712
SOT-223 [mm]
  rect 1.1x1.75 smd: 1(-2.3,-3.3) 2(0,-3.3) 3(2.3,-3.3)
  rect 3.5x1.75 smd: 4(0,3.3)
  silkscreen extent -3.35,-4.85 3.35,1.85
VO20 [mm] "20-Pin Thin Small-Outline Package (VO20)"
  rect 0.3x1.65 smd: 1(-2.925,-2.775) 2(-2.275,-2.775) 3(-1.625,-2.775) 4(-0.975,-2.775) 5(-0.325,-2.775) 6(0.325,-2.775) 7(0.975,-2.775) 8(1.625,-2.775) 9(2.275,-2.775) 10(2.925,-2.775) 11(2.925,2.775) 12(2.275,2.775) 13(1.625,2.775) 14(0.975,2.775) 15(0.325,2.775) 16(-0.325,2.775) 17(-0.975,2.775) 18(-1.625,2.775) 19(-2.275,2.775) 20(-2.925,2.775)
  silkscreen extent -3.75,-2.9 3.3,1.55

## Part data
C1 C2 C3 C4 C5 C6 C85 C86 C87 C88: library part Cap2, "Capacitor"
C7 C8 C9 C10 C11 C12 C13 C14 C15 C16 C17 C18 C19 C22 C25 C28 C29 C30 C31 C32 C33 C34 C35 C36 C39 C40 C41 C42 C43 C44 C45 C46 C47 C48 C49 C50 C51 C52 C53 C54 C68 C69 C70 C89 C90 C91 C92 C93 C94 C95 C96 C97 C98 C99 C100 C101 C102 C103 C104 C105 C106 C109 C110 C111 C112: library part Cap, "Capacitor"
D2 D3 D4: "General LED"
H1 H2: "Mounting Hole"
J1 J2 J3: "Header, 32-Pin, Dual row"
J4 J5: library part "Connector 2X25", "Connector, 25-Pin, Dual row"
J6 J7: "Connector, 5-Pin, Dual row"
J8: "AMP RJ45 8 Pin CAT5"
J10: "14 Position MDR Connector"
L1 L2 L3 L4 L5 L6 L7 L8 L9 L10 L11 L12 L13 L16 L19 L22: library part Inductor, "Inductor"
R1 R2 R3 R4 R5 R6 R7 R8 R9 R10 R11 R12 R13 R14 R15 R16 R17 R18 R19 R20 R22 R23 R24: library part Resistor, "Resistor"
U1: "Virtex-II Pro Platform FPGA, 456-Ball FBGA, Speed Grade 5, 248 User I/Os, Commercial Grade"
U2 U3: "Dual LVTTL/LVCMOS to Differential LVPECL Translator"
U4 U5 U6 U8: library part LT1963AEST-xx, "Three-Terminal LDO Positive Voltage Regulator"
U7: "XCF00S Series, Platform Flash In-System Programmable Configuration 3.3V PROM, 20-Pin TSOP, 4-Megabit, Commercial Grade"

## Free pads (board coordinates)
  round 39.37 hole 19.68: 0(-1251.97,-590.55) 0(-1241.1,-137.8) 0(-1241.1,413.39) 0(-1122.05,-670.24) 0(-1122.05,-550.24) 0(-1121.1,-137.8) 0(-1121.1,413.39) 0(-992.13,-681.1) 0(-992.13,-590.55) 0(-992.13,-500) 0(-964.57,530.55) 0(-964.57,650.55) 0(-582.68,-681.1) 0(-582.68,-590.55) 0(-582.68,-500) 0(-582.68,500) 0(-582.68,590.55) 0(-582.68,681.1) 0(-452.76,-670.24) 0(-452.76,-550.24) 0(-452.76,550.24) 0(-452.76,670.24) 0(-322.83,-590.55) 0(-322.83,590.55) 0(-169.29,500) 0(-169.29,590.55) 0(-169.29,681.1) 0(-39.37,550.24) 0(-39.37,670.24) 0(19.68,-680.08) 0(19.68,-560.08) 0(90.55,590.55) 0(255.91,551.18) 0(255.91,669.29) 0(3256.93,433.07) 0(3376.93,433.07)
  round 19.68 hole 9.84: 0(-958.66,-354.33) 0(-958.66,-275.59) 0(-958.66,-196.85) 0(-958.66,-118.11) 0(-958.66,118.11) 0(-958.66,196.85) 0(-958.66,275.59) 0(-958.66,354.33) 0(-761.81,-314.96) 0(-761.81,-236.22) 0(-761.81,-157.48) 0(-761.81,-78.74) 0(-761.81,78.74) 0(-761.81,157.48) 0(-761.81,236.22) 0(-761.81,314.96) 0(-604.33,0) 0(-595.87,-393.7) 0(-595.87,-314.96) 0(-595.87,-236.22) 0(-595.87,-157.48) 0(-595.87,-78.74) 0(-595.87,78.74) 0(-595.87,157.48) 0(-595.87,236.22) 0(-595.87,314.96) 0(-595.87,393.7) 0(-545.87,-393.7) 0(-545.87,393.7) 0(-442.91,-314.96) 0(-442.91,-236.22) 0(-442.91,-157.48) 0(-442.91,-78.74) 0(-442.91,78.74) 0(-442.91,157.48) 0(-442.91,236.22) 0(-442.91,314.96) 0(-393.85,709) 0(42.15,675) 0(118.15,439) 0(146.15,-29) 0(217.15,452) 0(233.27,-629.92) 0(260.15,-439) 0(283.27,-629.92) 0(312.65,-476.5) 0(315.15,569) 0(322.35,-710) 0(388.15,-455.5) 0(400.79,-650) 0(400.79,-600) 0(400.79,-550) 0(400.79,550) 0(400.79,600) 0(400.79,700) 0(439.15,374) 0(453.15,461) 0(469.69,550) 0(469.69,650) 0(470.15,-488) 0(472.65,-615) 0(475.15,-374) 0(486.81,452.76) 0(502.15,-485) 0(506.15,-408) 0(507.15,-19) 0(531.15,-648) 0(536.61,550) 0(536.61,650) 0(536.81,452.76) 0(596.15,366) 0(605.51,600) 0(608.15,245) 0(665.15,-619) 0(740.15,675) 0(795.65,-550) 0(795.65,-450) 0(795.65,-350) 0(795.65,-250) 0(795.65,-150) 0(795.65,-50) 0(795.65,50) 0(795.65,150) 0(795.65,250) 0(795.65,350) 0(795.65,450) 0(930.65,550) 0(1081.54,-365) 0(1082.68,-25) 0(1082.68,25) 0(1082.68,59.06) 0(1082.68,177.17) 0(1122.05,-165.35) 0(1148.47,-365) 0(1161.42,-258.46) 0(1161.42,-25) 0(1161.42,25) 0(1162.4,60.04) 0(1168.31,177.17) 0(1209.65,-24.61) 0(1219.49,167.32) 0(1239.15,453) 0(1240.16,-25) 0(1240.16,25) 0(1253.15,-158) 0(1273.62,-179.13) 0(1325,125) 0(1328.74,-346.46) 0(1334.65,-151.57) 0(1415.65,-550) 0(1415.65,-450) 0(1415.65,-350) 0(1415.65,-250) 0(1415.65,-150) 0(1415.65,-50) 0(1415.65,50) 0(1415.65,150) 0(1415.65,250) 0(1415.65,350) 0(1415.65,450) 0(1550.65,-200) 0(1550.65,-100) 0(1550.65,0) 0(1550.65,100) 0(1550.65,200) 0(1550.65,300) 0(1550.65,550) 0(1600.39,731.3) 0(1630,-250) 0(1650,260) 0(1650,290) 0(1654.53,641.73) 0(1655,-455) 0(1675,-270) 0(1698.82,-118.11) 0(1698.82,-39.37) 0(1698.82,39.37) 0(1698.82,118.11) 0(1702,-300) 0(1725,-325) 0(1738.65,520) 0(1740.16,-677.17) 0(1761.15,552) 0(1765.75,-118.11) 0(1765.75,-39.37) 0(1765.75,39.37) 0(1765.75,118.11) 0(1771.65,-188.98) 0(1795.28,-681.1) 0(1843.15,-577.5) 0(1843.15,-442.5) 0(1843.15,442.5) 0(1843.15,577.5) 0(1883.15,-75) 0(1893.15,-577.5) 0(1893.15,-442.5) 0(1893.15,442.5) 0(1893.15,577.5) 0(1942.15,-324) 0(1943.15,-577.5) 0(1943.15,-442.5) 0(1943.15,442.5) 0(1943.15,577.5) 0(1945.4,-208.75) 0(1949.15,-169) 0(1990.15,-305) 0(1993.15,-577.5) 0(1993.15,-442.5) 0(1993.15,442.5) 0(1993.15,577.5) 0(2013.78,-118.11) 0(2013.78,-39.37) 0(2013.78,39.37) 0(2013.78,118.11) 0(2041.5,217) 0(2043.15,-577.5) 0(2043.15,-442.5) 0(2043.15,442.5) 0(2043.15,577.5) 0(2061.15,-291) 0(2074.15,477) 0(2080.71,-118.11) 0(2080.71,-39.37) 0(2080.71,39.37) 0(2080.71,118.11) 0(2082.15,-472.4) 0(2101.15,197) 0(2108.15,-334) 0(2121.65,275) 0(2133.65,-433) 0(2134.15,409.5) 0(2195.32,-610.24) 0(2195.32,-570.87) 0(2195.32,-177.16) 0(2195.32,-137.79) 0(2195.32,-98.42) 0(2195.32,-59.05) 0(2195.32,-19.68) 0(2195.32,19.69) 0(2195.32,59.06) 0(2195.32,98.43) 0(2195.32,137.8) 0(2195.32,177.17) 0(2195.32,570.87) 0(2195.32,610.24) 0(2254.15,-545) 0(2256.15,430) 0(2257.56,-255.91) 0(2262.23,-334.65) 0(2268.65,207) 0(2271.65,-362) 0(2275.15,-436.5) 0(2279.15,-406) 0(2280.15,-315) 0(2280.15,-119) 0(2281.15,531.5) 0(2282.15,427) 0(2318.15,-695) 0(2340.98,-610.24) 0(2340.98,-570.87) 0(2340.98,-177.16) 0(2340.98,-137.79) 0(2340.98,-98.42) 0(2340.98,-59.05) 0(2340.98,-19.68) 0(2340.98,19.69) 0(2340.98,59.06) 0(2340.98,98.43) 0(2340.98,137.8) 0(2340.98,177.17) 0(2340.98,570.87) 0(2340.98,610.24) 0(2399.89,451.5) 0(2402.15,-545.5) 0(2407.4,-406.75) 0(2410.15,-126) 0(2422.15,-478) 0(2433.65,-587.47) 0(2435.15,501) 0(2445.65,403.5) 0(2450.15,207) 0(2458.57,-433) 0(2472.15,-264) 0(2480.15,213) 0(2487.15,451) 0(2490.65,-574.06) 0(2495.15,-413.39) 0(2496.91,531.5) 0(2497.15,-175) 0(2509.15,160.32) 0(2512.07,397.42) 0(2521.65,511.63) 0(2522.15,-357.5) 0(2528.15,191) 0(2528.28,-511) 0(2534.15,-236.04) 0(2536.15,216.54) 0(2595.32,-610.24) 0(2595.32,-570.87) 0(2595.32,-177.16) 0(2595.32,-137.79) 0(2595.32,-98.42) 0(2595.32,-59.05) 0(2595.32,-19.68) 0(2595.32,19.69) 0(2595.32,59.06) 0(2595.32,98.43) 0(2595.32,137.8) 0(2595.32,177.17) 0(2595.32,570.87) 0(2595.32,610.24) 0(2657.15,-148) 0(2657.74,209) 0(2660.61,183) 0(2662.15,-374.02) 0(2666.49,531.5) 0(2672.15,452.5) 0(2675.15,-280.5) 0(2677.33,-334.65) 0(2678.15,403.5) 0(2678.15,557) 0(2679.15,-612) 0(2740.98,-610.24) 0(2740.98,-570.87) 0(2740.98,-177.16) 0(2740.98,-137.79) 0(2740.98,-98.42) 0(2740.98,-59.05) 0(2740.98,-19.68) 0(2740.98,19.69) 0(2740.98,59.06) 0(2740.98,98.43) 0(2740.98,137.8) 0(2740.98,177.17) 0(2740.98,570.87) 0(2740.98,610.24) 0(2801.15,-591) 0(2801.15,-465.26) 0(2802.15,276) 0(2802.15,444) 0(2816.15,159) 0(2820.15,-445) 0(2827.15,-599) 0(2838.15,209.5) 0(2839.91,-548) 0(2844.15,322) 0(2848.15,-265) 0(2852.15,-410) 0(2860.15,-310.81) 0(2866.33,-244.96) 0(2874.65,217) 0(2875.65,-190) 0(2882.15,379) 0(2889.99,-410.48) 0(2894.65,330.5) 0(2895.57,-98.42) 0(2910.65,393.52) 0(2920.26,-413.39) 0(2926.49,315) 0(2933.15,-350) 0(2995.32,-610.24) 0(2995.32,-570.87) 0(2995.32,-531.5) 0(2995.32,-177.16) 0(2995.32,-137.79) 0(2995.32,-19.68) 0(2995.32,177.17) 0(2995.32,216.54) 0(2995.32,255.91) 0(2995.32,295.28) 0(2995.32,334.65) 0(2995.32,374.02) 0(2995.32,413.39) 0(2995.32,452.76) 0(2995.32,492.13) 0(2995.32,531.5) 0(2995.32,570.87) 0(2995.32,610.24) 0(3056.15,197) 0(3056.15,512) 0(3063.91,452.76) 0(3072.15,309.59) 0(3075.15,-287) 0(3079.15,-465) 0(3082.15,-204) 0(3140.98,-610.24) 0(3140.98,-570.87) 0(3140.98,98.43) 0(3140.98,137.8) 0(3140.98,177.17) 0(3140.98,570.87) 0(3140.98,610.24) 0(3199.15,-269) 0(3200.15,-335) 0(3202.15,26) 0(3217.1,-92) 0(3227.15,-408) 0(3230.28,-185.19) 0(3236.02,-374.02) 0(3255,-615) 0(3261.93,610.24) 0(3274.15,-371) 0(3285.15,-664) 0(3300.09,181.19) 0(3300.09,259.93) 0(3371.93,610.24) 0(3431.1,-551.18) 0(3498.03,-472.44) 1(605.51,550)

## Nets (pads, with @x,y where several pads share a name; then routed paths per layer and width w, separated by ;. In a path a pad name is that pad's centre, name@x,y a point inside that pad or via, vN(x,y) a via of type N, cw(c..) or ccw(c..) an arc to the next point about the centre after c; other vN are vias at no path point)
+1.5V: C29.1 C30.1 C31.1 C32.1 C33.1 C34.1 C35.1 C36.1 C87.1 D2.1 pad.0@255.91,551.18 pad.0@-169.29,500 U1.F6 U1.F17 U1.G7 U1.G8 U1.G15 U1.G16 U1.H7 U1.H16 U1.R7 U1.R16 U1.T7 U1.T8 U1.T15 U1.T16 U1.U6 U1.U17 U8.3 | length 284.4
  Top Layer w6: C34.1@98.43,-255.91 98.43,-246.06 108.27,-236.22 196.85,-236.22 U1.U17@216.54,-216.54 ; C35.1@98.43,255.91 98.43,239.17 101.38,236.22 196.85,236.22 U1.U6@216.54,216.54
+2.5V: C86.1 C89.1 C90.1 C91.1 C92.1 C93.1 C94.1 C95.1 C96.1 C97.1 C98.1 C99.1 C100.1 C101.1 C102.1 C103.1 C104.1 C105.1 C106.1 C109.1 C110.1 C111.1 C112.1 D3.1 J3.54 J3.56 J3.58 pad.0@19.68,-560.08 pad.0@1081.54,-365 pad.0@1082.68,177.17 pad.0@1082.68,-25 pad.0@1122.05,-165.35 pad.0@1161.42,-25 pad.0@2995.32,413.39 pad.0@2995.32,452.76 pad.0@2995.32,492.13 pad.0@-545.87,393.7 pad.0@-545.87,-393.7 R13.1 R20.2 R22.2 R23.2 R24.2 U1.A12 U1.AA2 U1.AA21 U1.AB11 U1.B2 U1.B21 U1.F7 U1.F8 U1.F15 U1.F16 U1.G6 U1.G9 U1.G10 U1.G11 U1.G12 U1.G13 U1.G14 U1.G17 U1.H6 U1.H17 U1.J7 U1.J16 U1.K7 U1.K16 U1.L1 U1.L7 U1.L16 U1.M7 U1.M16 U1.M22 U1.N7 U1.N16 U1.P7 U1.P16 U1.R6 U1.R17 U1.T6 U1.T9 U1.T10 U1.T11 U1.T12 U1.T13 U1.T14 U1.T17 U1.U7 U1.U8 U1.U15 U1.U16 U7.19 U7.20 | length 4685.1
  Top Layer w6: R13.1@-537.4,0 -433.07,0 U1.A12@-413.39,-19.68 C106.1@-334.65,-19.68 ; U1.B21@-374.02,-374.02 -363.39,-384.65 C109.1@-363.39,-413.39 ; U1.B2@-374.02,374.02 -363.39,384.65 C110.1@-363.39,413.39 ; C103.1@363.39,-413.39 363.39,-384.65 U1.AA21@374.02,-374.02 ; C111.1@363.39,413.39 374.02,402.76 U1.AA2@374.02,374.02 ; R24.2@1082.68,-191.54 1095.87,-191.54 pad.0@1122.05,-165.35 1148.23,-191.54 R20.2@1161.42,-191.54
  MidLayer2 w6: pad.0@1081.54,-365 1081.54,-205.87 pad.0@1122.05,-165.35
  MidLayer2 w19.68: pad.0@-545.87,-393.7 -452.25,-393.7 -432.57,-374.02 U1.B21@-374.02,-374.02 ; pad.0@-545.87,393.7 -450.41,393.7 -430.72,374.02 U1.B2@-374.02,374.02 ; pad.0@1082.68,-25 1124.41,-25 ; 1124.41,305.12 1124.41,-25 ; pad.0@1161.42,-25 1124.41,-25 ; pad.0@2995.32,413.39 pad.0@2995.32,452.76 pad.0@2995.32,492.13
  MidLayer2 w20: pad.0@1082.68,177.17 1121.58,177.17
  MidLayer2 w40: pad.0@19.68,-560.08 U1.M22@19.69,-413.39
  MidLayer2 w50: 413.39,305.12 1124.41,305.12 1455.12,305.12 1500,350 2783.47,350 2886.22,452.76 pad.0@2995.32,452.76
  Bottom Layer w6: U7.19@1091.54,-109.25 1091.54,-158.46 1098.43,-165.35 pad.0@1122.05,-165.35
  Bottom Layer w8: U7.20@1065.95,-109.25 1065.95,-41.73 pad.0@1082.68,-25 ; U7.19@1091.54,-109.25 1091.54,-62.4 1128.94,-25 pad.0@1161.42,-25
+3.3V: C1.1 C2.1 C3.1 C68.1 C69.1 C70.1 C85.1 C88.1 D4.1 J3.1 J3.2 J3.3 J3.4 J3.6 J3.60 J3.61 J3.62 J3.63 J3.64 J6.1 J6.2 J6.3 J6.4 J6.5 J7.1 J7.2 J7.3 J7.4 J7.5 pad.0@283.27,-629.92 pad.0@322.35,-710 pad.0@400.79,550 pad.0@486.81,452.76 pad.0@1240.16,-25 pad.0@1843.15,442.5 pad.0@1843.15,-577.5 pad.0@1893.15,442.5 pad.0@1893.15,-577.5 pad.0@1943.15,442.5 pad.0@1943.15,-577.5 pad.0@1993.15,442.5 pad.0@1993.15,-577.5 pad.0@2043.15,442.5 pad.0@2043.15,-577.5 pad.0@2080.71,39.37 pad.0@2080.71,118.11 pad.0@2080.71,-39.37 pad.0@2080.71,-118.11 pad.0@2995.32,531.5 pad.0@2995.32,570.87 pad.0@2995.32,610.24 pad.0@2995.32,-531.5 pad.0@2995.32,-570.87 pad.0@2995.32,-610.24 pad.0@3140.98,570.87 pad.0@3140.98,610.24 pad.0@3140.98,-570.87 pad.0@3140.98,-610.24 pad.0@3371.93,610.24 pad.0@3376.93,433.07 pad.0@-39.37,670.24 pad.0@-169.29,681.1 pad.0@-452.76,670.24 pad.0@-452.76,-550.24 pad.0@-582.68,681.1 pad.0@-582.68,-500 pad.0@-992.13,-681.1 pad.0@-1122.05,-670.24 R1.1 R2.1 R3.1 R4.1 U2.8 U3.8 U4.1 U5.1 U6.1 U7.18 U8.1 | length 265.7
  Top Layer w6: pad.0@322.35,-710 335.59,-710 345.59,-700 U3.8@400.79,-700
  Bottom Layer w8: U7.18@1117.13,-109.25 1117.13,-66.34 1124.41,-59.06 1206.1,-59.06 pad.0@1240.16,-25
\A: C39.1 C40.1 J10.9 | length 1107.8
  Bottom Layer w6: C40.1@-851.77,265.75 -905.51,265.75 -982.09,342.33 -1134.05,342.33 -1181.1,295.28 -1181.1,265.75 -1211.85,235 J10.9@-1301.85,235 -1301.85,282.8 -1141.73,442.91 C39.1@-851.77,442.91
\B: C45.1 C46.1 J10.2 | length 858.4
  Bottom Layer w6: C45.1@-851.77,29.53 -954.72,29.53 -994.09,68.9 -994.09,167.32 -1061.77,235 J10.2@-1151.85,235 -1151.85,285.16 -1112.2,324.8 -1043.31,324.8 -925.2,206.69 C46.1@-851.77,206.69
\C: C49.1 C50.1 J10.6 | length 753.1
  Bottom Layer w6: C49.1@-851.77,-206.69 -895.67,-206.69 -944.88,-157.48 -1003.94,-157.48 -1151.85,-9.57 J10.6@-1151.85,35 -1019.25,35 -954.72,-29.53 C50.1@-851.77,-29.53
\D: C51.1 C52.1 J10.13 | length 1347.9
  Bottom Layer w6: C51.1@-851.77,-442.91 -935.04,-442.91 -984.25,-393.7 -984.25,-324.8 -1084.37,-224.69 -1123.74,-224.69 -1181.1,-167.32 -1181.1,-127.95 -1223.31,-85.75 -1266.85,-85.75 -1301.85,-50.75 J10.13@-1301.85,35 -1216.1,35 -1181.1,0 -1181.1,-19.68 -935.04,-265.75 C52.1@-851.77,-265.75
\RX_A: C40.2 U1.A6 | length 412
  Bottom Layer w6: C40.2@-801.77,265.75 -718.5,265.75 -665.35,212.6 -448.82,212.6 -444.88,216.54 U1.A6@-413.39,216.54
\RX_B: C45.2 U1.A10 | length 400.6
  Bottom Layer w6: C45.2@-801.77,29.53 -718.5,29.53 -698.82,49.21 -423.23,49.21 U1.A10@-413.39,59.06
\RX_C: C49.2 U1.A16 | length 400.6
  Bottom Layer w6: C49.2@-801.77,-206.69 -718.5,-206.69 -698.82,-187.01 -423.23,-187.01 U1.A16@-413.39,-177.17
\RX_D: C51.2 U1.A20 | length 433.2
  Bottom Layer w6: C51.2@-801.77,-442.91 -718.5,-442.91 -620.08,-344.49 -423.23,-344.49 U1.A20@-413.39,-334.65
\TX_A: C39.2 U1.A3 | length 433.2
  Bottom Layer w6: C39.2@-801.77,442.91 -718.5,442.91 -620.08,344.49 -423.23,344.49 U1.A3@-413.39,334.65
\TX_B: C46.2 U1.A7 | length 400.6
  Bottom Layer w6: C46.2@-801.77,206.69 -718.5,206.69 -692.91,181.1 -448.82,181.1 -444.88,177.17 U1.A7@-413.39,177.17
\TX_C: C50.2 U1.A13 | length 400.6
  Bottom Layer w6: C50.2@-801.77,-29.53 -718.5,-29.53 -698.82,-49.21 -423.23,-49.21 U1.A13@-413.39,-59.06
\TX_D: C52.2 U1.A17 | length 416.9
  Bottom Layer w6: C52.2@-801.77,-265.75 -718.5,-265.75 -659.45,-206.69 -423.23,-206.69 U1.A17@-413.39,-216.54
A: C41.1 C42.1 J10.8 | length 476.7
  Bottom Layer w6: J10.8@-1226.85,285 -1157.52,354.33 -1023.62,354.33 -1003.94,374.02 -915.35,374.02 -895.67,354.33 -866.14,354.33 ; C42.1@-851.77,324.8 -851.77,339.96 -866.14,354.33 ; C41.1@-851.77,383.86 -851.77,368.7 -866.14,354.33
AVCCAUX: C4.1 L1.2 L4.2 L7.2 L10.2 L13.2 L16.2 L19.2 L22.2 pad.0@-761.81,78.74 pad.0@-761.81,157.48 pad.0@-761.81,236.22 pad.0@-761.81,314.96 pad.0@-958.66,-118.11 pad.0@-958.66,-196.85 pad.0@-958.66,-275.59 pad.0@-958.66,-354.33 pad.0@-992.13,-500 pad.0@-1121.1,-137.8 U4.3 | length 1081
  MIdLayer5 w19.68: pad.0@-1121.1,-137.8 -1043.31,-137.8 -1023.62,-118.11 pad.0@-958.66,-118.11 ; pad.0@-992.13,-500 -992.13,-421.26 -958.66,-387.8 pad.0@-958.66,-354.33 pad.0@-958.66,-275.59 pad.0@-958.66,-196.85 pad.0@-958.66,-118.11 ; pad.0@-761.81,314.96 pad.0@-761.81,236.22 pad.0@-761.81,157.48 pad.0@-761.81,78.74 pad.0@-958.66,-118.11
AVCCAUX1: C7.1 L1.1 pad.0@-442.91,314.96 U1.B4 | length 469.7
  Top Layer w10: L1.1@-694.88,314.96 -649.61,314.96 -620.08,285.43 -442.91,285.43 ; pad.0@-442.91,314.96 -442.91,285.43 ; U1.B4@-374.02,295.28 -383.86,285.43 -442.91,285.43
  Bottom Layer w10: C7.1@-545.87,314.96 pad.0@-442.91,314.96
AVCCAUX2: C10.1 L4.1 pad.0@-442.91,236.22 U1.B6 | length 469.7
  Top Layer w10: L4.1@-694.88,236.22 -649.61,236.22 -620.08,206.69 -442.91,206.69 ; pad.0@-442.91,236.22 -442.91,206.69 ; U1.B6@-374.02,216.54 -383.86,206.69 -442.91,206.69
  Bottom Layer w10: C10.1@-545.87,236.22 pad.0@-442.91,236.22
AVCCAUX3: C13.1 L7.1 pad.0@-442.91,157.48 U1.B8 | length 469.7
  Top Layer w10: L7.1@-694.88,157.48 -649.61,157.48 -620.08,127.95 -442.91,127.95 ; pad.0@-442.91,157.48 -442.91,127.95 ; U1.B8@-374.02,137.8 -383.86,127.95 -442.91,127.95
  Bottom Layer w10: C13.1@-545.87,157.48 pad.0@-442.91,157.48
AVCCAUX4: C16.1 L10.1 pad.0@-442.91,78.74 U1.B10 | length 469.7
  Top Layer w10: L10.1@-694.88,78.74 -649.61,78.74 -620.08,49.21 -442.91,49.21 ; pad.0@-442.91,78.74 -442.91,49.21 ; U1.B10@-374.02,59.06 -383.86,49.21 -442.91,49.21
  Bottom Layer w10: C16.1@-545.87,78.74 pad.0@-442.91,78.74
AVCCAUX5: C19.1 L13.1 U1.B14 | length 557.6
  Top Layer w10: L13.1@-891.73,-118.11 -639.76,-118.11 -629.92,-108.27 -551.18,-108.27 ; C19.1@-545.87,-78.74 -545.87,-102.95 -551.18,-108.27 ; U1.B14@-374.02,-98.43 -383.86,-108.27 -551.18,-108.27
AVCCAUX6: C22.1 L16.1 U1.B16 | length 557.6
  Top Layer w10: L16.1@-891.73,-196.85 -639.76,-196.85 -629.92,-187.01 -551.18,-187.01 ; C22.1@-545.87,-157.48 -545.87,-181.69 -551.18,-187.01 ; U1.B16@-374.02,-177.17 -383.86,-187.01 -551.18,-187.01
AVCCAUX7: C25.1 L19.1 U1.B18 | length 557.6
  Top Layer w10: L19.1@-891.73,-275.59 -639.76,-275.59 -629.92,-265.75 -551.18,-265.75 ; C25.1@-545.87,-236.22 -545.87,-260.43 -551.18,-265.75 ; U1.B18@-374.02,-255.91 -383.86,-265.75 -551.18,-265.75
